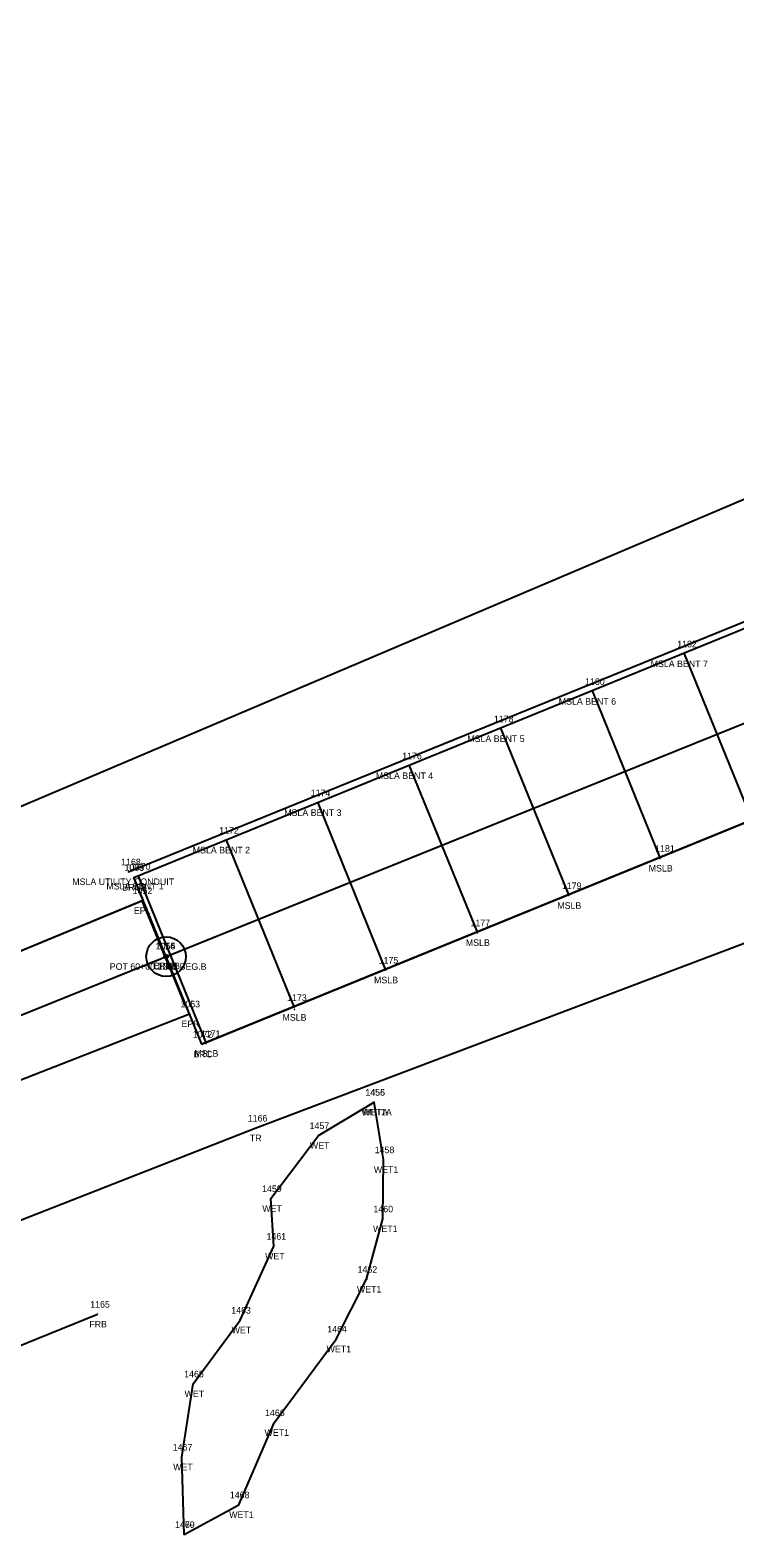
# Model space of a CAD drawing. Extents: x 1964982 to 1970452, y 1116335 to 1119906.
# Drawn here: x 1967677.5 to 1967784.4, y 1117734.5 to 1117963.3 of the extents above; entities that cross this region are included whole.
import ezdxf

# ---------------------------------------------------------------- set-up
doc = ezdxf.new("R2010")
doc.units = 0
for name, color, linetype in [('RD_EX_Bridge', 7, 'Continuous'), ('RD_EX_Bridge_txCode', 7, 'Continuous'), ('RD_EX_DV_Prop', 7, 'Continuous'), ('RD_EX_Fence_Other', 7, 'Continuous'), ('RD_EX_Fence_Other_txCode', 7, 'Continuous'), ('RD_EX_H2O_WetLd', 7, 'Continuous'), ('RD_EX_H2O_WetLd_txCode', 7, 'Continuous'), ('RD_EX_Misc', 7, 'Continuous'), ('RD_EX_Misc_txCode', 7, 'Continuous'), ('RD_EX_Road', 7, 'Continuous'), ('RD_EX_Road_txCode', 7, 'Continuous'), ('RD_EX_RW', 7, 'Continuous'), ('RD_EX_VEG', 7, 'Continuous'), ('RD_EX_VEG_txCode', 7, 'Continuous'), ('RD_HC_CL', 7, 'Continuous'), ('RD_HC_Data', 7, 'Continuous'), ('RD_HC_Data_Tic', 7, 'Continuous'), ('RD_HC_txCode', 7, 'Continuous'), ('RD_SMD_Locator', 7, 'Continuous'), ('RD_SMD_Misc', 7, 'Continuous')]:
    doc.layers.add(name, color=color, linetype=linetype)

msp = doc.modelspace()

# ---------------------------------------------------------------- linework, layer by layer
at = {"layer": 'RD_EX_Bridge'}
msp.add_lwpolyline([(1967693.16, 1117834.73), (1967873.65, 1117908.38), (1967883.99, 1117883.05), (1967703.5, 1117809.4), (1967693.16, 1117834.73)], dxfattribs=at)
at = {"layer": 'RD_EX_DV_Prop'}
for p, q in [((1967698.07, 1117822.7), (1967825.19, 1117874.05)), ((1966770.74, 1117448.12), (1967698.07, 1117822.7))]:
    msp.add_line(p, q, dxfattribs=at)
at = {"layer": 'RD_EX_Fence_Other'}
msp.add_lwpolyline([(1967532.54, 1117707.33), (1967583.14, 1117726.03), (1967687.66, 1117768.42)], dxfattribs=at)
at = {"layer": 'RD_EX_H2O_WetLd'}
for points in [[(1967700.81, 1117734.98), (1967700.46, 1117746.73), (1967702.19, 1117757.84), (1967709.33, 1117767.52), (1967714.4, 1117778.74), (1967713.99, 1117785.97), (1967721.2, 1117795.54), (1967729.67, 1117800.6)], [(1967700.81, 1117734.98), (1967709.12, 1117739.49), (1967714.48, 1117751.96), (1967723.9, 1117764.65), (1967728.5, 1117773.72), (1967730.95, 1117782.89), (1967731.07, 1117791.87), (1967729.67, 1117800.6)]]:
    msp.add_lwpolyline(points, dxfattribs=at)
at = {"layer": 'RD_EX_Misc'}
for p, q in [((1967692.35, 1117835.57), (1967874.47, 1117909.58)), ((1967776.68, 1117868.65), (1967786.99, 1117843.32)), ((1967762.76, 1117862.95), (1967773.06, 1117837.62)), ((1967748.87, 1117857.28), (1967759.19, 1117831.96)), ((1967734.98, 1117851.66), (1967745.32, 1117826.32)), ((1967721.09, 1117846.06), (1967731.39, 1117820.65)), ((1967707.21, 1117840.37), (1967717.5, 1117814.98)), ((1967693.82, 1117834.9), (1967704.14, 1117809.51))]:
    msp.add_line(p, q, dxfattribs=at)
at = {"layer": 'RD_EX_Road'}
for points in [[(1966769.51, 1117457.48), (1966870.16, 1117497.34), (1966971.19, 1117538.95), (1967071.09, 1117580.24), (1967172.6, 1117621.53), (1967270.79, 1117661.66), (1967321.12, 1117682.57), (1967371.52, 1117702.88), (1967470.26, 1117741.55), (1967566.67, 1117779.5), (1967661.25, 1117817.53), (1967694.4, 1117831.19), (1967697.89, 1117822.8)], [(1967302.16, 1117654.09), (1967379.26, 1117686.2), (1967476.09, 1117724.39), (1967573.92, 1117763.51), (1967667.7, 1117800.74), (1967701.64, 1117814), (1967697.89, 1117822.8)]]:
    msp.add_lwpolyline(points, dxfattribs=at)
at = {"layer": 'RD_EX_RW'}
for p, q in [((1967783.4, 1117871.55), (1967873.65, 1117908.38)), ((1967693.16, 1117834.73), (1967783.4, 1117871.55)), ((1967703.5, 1117809.4), (1967793.74, 1117846.23)), ((1967694.58, 1117831.26), (1967693.16, 1117834.73)), ((1967703.5, 1117809.4), (1967701.62, 1117814))]:
    msp.add_line(p, q, dxfattribs=at)
for points in [[(1966769.51, 1117457.48), (1966870.16, 1117497.34), (1966971.19, 1117538.95), (1967071.09, 1117580.24), (1967172.6, 1117621.53), (1967270.79, 1117661.66), (1967321.12, 1117682.57), (1967371.52, 1117702.88), (1967470.26, 1117741.55), (1967566.67, 1117779.5), (1967661.25, 1117817.53), (1967694.56, 1117831.26)], [(1967302.16, 1117654.09), (1967379.26, 1117686.2), (1967476.09, 1117724.39), (1967573.92, 1117763.51), (1967667.7, 1117800.74), (1967701.64, 1117814)]]:
    msp.add_lwpolyline(points, dxfattribs=at)
at = {"layer": 'RD_EX_VEG'}
for points in [[(1967422.03, 1117809.72), (1967453.38, 1117748.92), (1967559.8, 1117796.17), (1967844.47, 1117917.07), (1967917.86, 1117947.25), (1968009.67, 1117958.84), (1968061.48, 1117958.08), (1968105.8, 1117963.33), (1968158.86, 1117956.79), (1968212.37, 1117954.08), (1968423.16, 1117946.63), (1968536.42, 1117942.26)], [(1967303.54, 1117601.01), (1967338.99, 1117640.22), (1967353.28, 1117654.56), (1967394.76, 1117667.24), (1967484.61, 1117707.66), (1967711.58, 1117796.67), (1967890.09, 1117864.21), (1967929.29, 1117872.68), (1967959.15, 1117877.99), (1967976.93, 1117884.5), (1968014.32, 1117894.35), (1968104.14, 1117889.87), (1968155.31, 1117895.48), (1968209.85, 1117895.88), (1968320.55, 1117893.51), (1968423.04, 1117892.22), (1968529.15, 1117876.96)]]:
    msp.add_lwpolyline(points, dxfattribs=at)
at = {"layer": 'RD_HC_CL'}
msp.add_line((1966770.74, 1117448.12), (1967849.47, 1117883.86), dxfattribs=at)
at = {"layer": 'RD_HC_Data'}
for radius in [3, 0.282]:
    msp.add_circle((1967698.07, 1117822.7), radius, dxfattribs=at)
at = {"layer": 'RD_HC_Data_Tic'}
for q in [(1967694.95, 1117830.07), (1967700.95, 1117815.24)]:
    msp.add_line((1967697.95, 1117822.66), q, dxfattribs=at)
at = {"layer": 'RD_SMD_Locator'}
for centre in [(1967776.68, 1117868.65), (1967762.76, 1117862.95), (1967748.87, 1117857.28), (1967734.98, 1117851.66), (1967721.09, 1117846.06), (1967707.21, 1117840.37), (1967692.35, 1117835.57), (1967773.06, 1117837.62), (1967693.16, 1117834.73), (1967693.16, 1117834.73), (1967693.82, 1117834.9), (1967694.4, 1117831.19), (1967759.19, 1117831.96), (1967745.32, 1117826.32), (1967697.89, 1117822.8), (1967697.89, 1117822.8), (1967697.89, 1117822.8), (1967698.07, 1117822.7), (1967731.39, 1117820.65), (1967717.5, 1117814.98), (1967701.64, 1117814), (1967717.54, 1117814.67), (1967703.5, 1117809.4), (1967704.14, 1117809.51), (1967729.67, 1117800.6), (1967729.67, 1117800.6), (1967711.58, 1117796.67), (1967721.2, 1117795.54), (1967731.07, 1117791.87), (1967713.99, 1117785.97), (1967730.95, 1117782.89), (1967714.4, 1117778.74), (1967728.5, 1117773.72), (1967687.66, 1117768.42), (1967709.33, 1117767.52), (1967723.9, 1117764.65), (1967702.19, 1117757.84), (1967714.48, 1117751.96), (1967700.46, 1117746.73), (1967709.12, 1117739.49), (1967700.81, 1117734.98), (1967700.81, 1117734.98)]:
    msp.add_circle(centre, 0.001, dxfattribs=at)

# ---------------------------------------------------------------- texts
at = {"layer": 'RD_EX_Bridge_txCode'}
for s, p in [('1069', (1967691.75, 1117835.73)), ('1073', (1967691.77, 1117835.73)), ('BRCA', (1967691.42, 1117832.73)), ('BRCB', (1967691.43, 1117832.73)), ('1072', (1967702.11, 1117810.4)), ('BRC', (1967702.25, 1117807.4))]:
    msp.add_text(s, height=1, dxfattribs=at).set_placement(p)
at = {"layer": 'RD_EX_Fence_Other_txCode'}
for s, p in [('1165', (1967686.57, 1117769.42)), ('FRB', (1967686.43, 1117766.42))]:
    msp.add_text(s, height=1, dxfattribs=at).set_placement(p)
at = {"layer": 'RD_EX_H2O_WetLd_txCode'}
for s, p in [('1456', (1967728.3, 1117801.6)), ('1455', (1967728.33, 1117801.6)), ('WET1A', (1967727.71, 1117798.6)), ('WETA', (1967727.88, 1117798.6)), ('1457', (1967719.85, 1117796.54)), ('WET', (1967719.89, 1117793.54)), ('1458', (1967729.73, 1117792.87)), ('WET1', (1967729.6, 1117789.87)), ('1459', (1967712.64, 1117786.97)), ('WET', (1967712.68, 1117783.97)), ('1460', (1967729.54, 1117783.89)), ('1461', (1967713.32, 1117779.74)), ('WET1', (1967729.48, 1117780.89)), ('WET', (1967713.1, 1117776.74)), ('1462', (1967727.13, 1117774.72)), ('WET1', (1967727.03, 1117771.72)), ('1463', (1967707.96, 1117768.52)), ('WET', (1967708.02, 1117765.52)), ('1464', (1967722.53, 1117765.65)), ('WET1', (1967722.43, 1117762.65)), ('1465', (1967700.82, 1117758.84)), ('WET', (1967700.88, 1117755.84)), ('1466', (1967713.09, 1117752.96)), ('WET1', (1967713.01, 1117749.96)), ('1467', (1967699.09, 1117747.73)), ('WET', (1967699.15, 1117744.73)), ('1468', (1967707.75, 1117740.49)), ('1470', (1967699.43, 1117735.98)), ('1469', (1967699.44, 1117735.98)), ('WET1', (1967707.65, 1117737.49))]:
    msp.add_text(s, height=1, dxfattribs=at).set_placement(p)
at = {"layer": 'RD_EX_Misc_txCode'}
for s, p in [('1182', (1967775.62, 1117869.65)), ('MSLA BENT 7', (1967771.59, 1117866.65)), ('1180', (1967761.65, 1117863.95)), ('MSLA BENT 6', (1967757.65, 1117860.95)), ('1178', (1967747.81, 1117858.28)), ('MSLA BENT 5', (1967743.78, 1117855.28)), ('1176', (1967733.9, 1117852.66)), ('MSLA BENT 4', (1967729.9, 1117849.66)), ('1174', (1967720.02, 1117847.06)), ('MSLA BENT 3', (1967716, 1117844.06)), ('1172', (1967706.14, 1117841.37)), ('MSLA BENT 2', (1967702.12, 1117838.37)), ('1181', (1967772.28, 1117838.62)), ('1168', (1967691.26, 1117836.57)), ('1170', (1967692.72, 1117835.9)), ('MSLB', (1967771.3, 1117835.62)), ('MSLA UTILITY CONDUIT', (1967683.84, 1117833.57)), ('MSLA BENT 1', (1967689.02, 1117832.9)), ('1179', (1967758.13, 1117832.96)), ('MSLB', (1967757.43, 1117829.96)), ('1177', (1967744.26, 1117827.32)), ('MSLB', (1967743.56, 1117824.32)), ('1175', (1967730.33, 1117821.65)), ('MSLB', (1967729.63, 1117818.65)), ('1173', (1967716.44, 1117815.98)), ('MSLB', (1967715.74, 1117812.98)), ('1171', (1967703.36, 1117810.51)), ('MSLB', (1967702.37, 1117807.51))]:
    msp.add_text(s, height=1, dxfattribs=at).set_placement(p)
at = {"layer": 'RD_EX_Road_txCode'}
for s, p in [('1052', (1967693.01, 1117832.19)), ('EPL', (1967693.19, 1117829.19)), ('1056', (1967696.48, 1117823.8)), ('1055', (1967696.51, 1117823.8)), ('EPRB', (1967696.19, 1117820.8)), ('EPLB', (1967696.22, 1117820.8)), ('1053', (1967700.25, 1117815)), ('EPR', (1967700.41, 1117812))]:
    msp.add_text(s, height=1, dxfattribs=at).set_placement(p)
at = {"layer": 'RD_EX_VEG_txCode'}
for s, p in [('1166', (1967710.47, 1117797.67)), ('TR', (1967710.79, 1117794.67))]:
    msp.add_text(s, height=1, dxfattribs=at).set_placement(p)
at = {"layer": 'RD_HC_txCode'}
for s, p in [('7', (1967697.79, 1117823.7)), ('POT 60+00.1268 BEG.B', (1967689.53, 1117820.7))]:
    msp.add_text(s, height=1, dxfattribs=at).set_placement(p)
at = {"layer": 'RD_SMD_Misc'}
for s, p in [('1054', (1967696.51, 1117823.8)), ('CRWB', (1967696.1, 1117820.8))]:
    msp.add_text(s, height=1, dxfattribs=at).set_placement(p)

doc.saveas('drawing.dxf')
